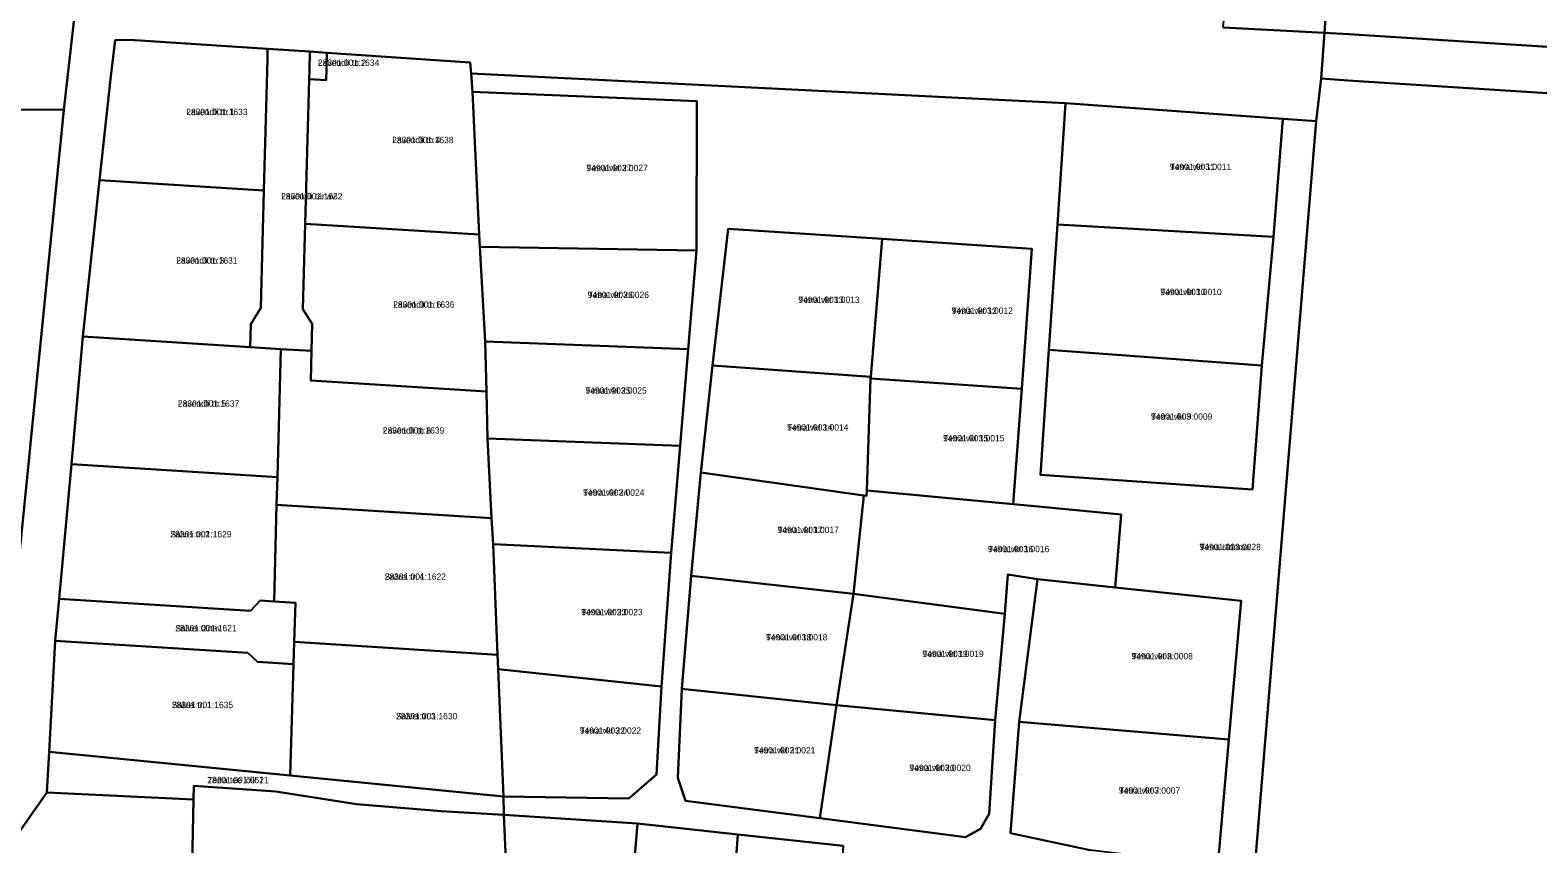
# Model space of a CAD drawing. Extents: x 647845 to 668483, y 6445298 to 6473683.
# Drawn here: x 653029 to 653385.7, y 6468442.7 to 6468635.3 of the extents above; entities that cross this region are included whole.
import ezdxf

# ---------------------------------------------------------------- set-up
doc = ezdxf.new("R2010")
doc.units = 0
for name, color, linetype in [('L_AADRESS', 7, 'Continuous'), ('PIIR', 7, 'Continuous'), ('TUNNUS', 7, 'Continuous')]:
    doc.layers.add(name, color=color, linetype=linetype)

msp = doc.modelspace()

# ---------------------------------------------------------------- linework, layer by layer
at = {"layer": 'PIIR'}
for points in [[(652338.93, 6468981.05), (652696.45, 6468730.7), (652794.83, 6468661.68), (653047.44, 6468736.3), (653049.27, 6468736.37), (653044.84, 6468694.9), (653040.96, 6468651.31), (653036.95, 6468616.44), (652921.22, 6468617.23), (652884.72, 6468617.47), (652848.22, 6468617.72), (652811.72, 6468617.97), (652775.22, 6468618.22), (652738.72, 6468618.47), (652702.23, 6468618.72), (652665.73, 6468618.96), (652629.23, 6468619.21), (652592.73, 6468619.46), (652556.23, 6468619.7), (652519.73, 6468619.96), (652483.23, 6468620.21), (652450.34, 6468620.43), (652403.65, 6468620.75), (652383.63, 6468708.25)], [(653025.07, 6468497.06), (653036.95, 6468616.44), (653040.96, 6468651.31)], [(653311.26, 6468635.95), (653335.23, 6468634.71), (653334.45, 6468623.86), (653333.23, 6468613.76), (653325.37, 6468614.34), (653273.95, 6468618.06), (653133.32, 6468625.06), (653133.14, 6468627.7), (653099.21, 6468629.97), (653095.18, 6468630.24), (653085.19, 6468630.9), (653052.6, 6468633.07), (653049.09, 6468632.99), (653048.14, 6468624.4), (653045.4, 6468599.8), (653041.46, 6468562.8), (653038.82, 6468532.6), (653035.87, 6468500.73), (653034.92, 6468490.77), (653033.49, 6468464.51), (653032.96, 6468454.83), (653015.66, 6468430.26)], [(653833.65, 6468592.05), (653340.7, 6468623.38), (653334.45, 6468623.86), (653335.23, 6468634.71), (653340.97, 6468634.35), (653661.32, 6468613.93)], [(653221.36, 6468442.23), (653196.46, 6468444.93), (653172.68, 6468447.5), (653141.05, 6468449.59), (653140.97, 6468453.86), (653170.63, 6468453.42), (653177.16, 6468459.07), (653178.36, 6468479.95), (653180.62, 6468511.57), (653182.76, 6468536.91), (653184.69, 6468559.77), (653186.67, 6468583.17), (653186.7, 6468618.5), (653133.63, 6468620.73), (653133.32, 6468625.06), (653273.95, 6468618.06), (653272.02, 6468589.3), (653270.03, 6468559.64), (653268.04, 6468530.08), (653318.16, 6468526.55), (653320.4, 6468555.9), (653323.12, 6468586.39), (653325.37, 6468614.34), (653333.23, 6468613.76), (653317.65, 6468423.77)], [(653710.59, 6468385.69), (653555.14, 6468400.78), (653531.19, 6468403.11), (653478.45, 6468408.19), (653472.23, 6468408.79), (653401.93, 6468415.57), (653339.11, 6468421.73), (653320.73, 6468423.39), (653317.65, 6468423.77), (653333.23, 6468613.76), (653334.45, 6468623.86), (653340.7, 6468623.38), (653833.65, 6468592.05)], [(653310.01, 6468437.56), (653312.6, 6468467.38), (653315.49, 6468500.22), (653285.66, 6468503.4), (653287.15, 6468520.69), (653267.46, 6468522.54), (653261.54, 6468523.1), (653263.61, 6468550.43), (653266.01, 6468583.55), (653230.6, 6468585.89), (653194.13, 6468588.29), (653190.47, 6468555.97), (653187.67, 6468530.64), (653185.36, 6468506.15), (653183.19, 6468479.41), (653182.21, 6468458.31), (653184.01, 6468452.89), (653215.79, 6468448.76), (653250.27, 6468444.31), (653253.8, 6468446.24), (653255.92, 6468449.81), (653257.34, 6468471.98), (653259.56, 6468497.15), (653260.27, 6468506.49), (653267.31, 6468505.34), (653262.98, 6468471.61), (653260.93, 6468445.19), (653279.74, 6468441.16)]]:
    msp.add_lwpolyline(points, dxfattribs=at)
for points in [[(653311.26, 6468635.95), (653312.47, 6468649.1), (653330.48, 6468649.07), (653333.16, 6468676.61), (653336.06, 6468705.49), (653338.28, 6468734.94), (653340.46, 6468764.79), (653342.62, 6468794.35), (653345.18, 6468824.85), (653347.75, 6468857.25), (653350.22, 6468888.19), (653352.64, 6468917.87), (653369.86, 6468979.89), (653374.26, 6468980.08), (653365.44, 6468948.31), (653356.91, 6468917.58), (653353.12, 6468866.71), (653346.11, 6468776.83), (653345.82, 6468772.19), (653342.65, 6468722.74), (653335.88, 6468644.68), (653335.23, 6468634.71)], [(653346.11, 6468776.83), (653515.43, 6468766.59), (653515.34, 6468764.64), (653676.65, 6468698.91), (653661.32, 6468613.93), (653340.97, 6468634.35), (653335.23, 6468634.71), (653335.88, 6468644.68), (653342.65, 6468722.74), (653345.82, 6468772.19)], [(653048.14, 6468624.4), (653049.09, 6468632.99), (653052.6, 6468633.07), (653085.19, 6468630.9), (653085.13, 6468628.35), (653084.3, 6468597.35), (653045.4, 6468599.8)], [(653085.13, 6468628.35), (653085.19, 6468630.9), (653095.18, 6468630.24), (653095.06, 6468625.69), (653095.01, 6468623.75), (653094.1, 6468589.49), (653093.56, 6468569.29), (653095.72, 6468565.76), (653095.55, 6468559.38), (653088.31, 6468559.84), (653081.07, 6468560.3), (653081.21, 6468565.7), (653083.56, 6468569.55), (653084.3, 6468597.35)], [(653099.1, 6468626.11), (653099.21, 6468629.97), (653133.14, 6468627.7), (653133.32, 6468625.06), (653133.63, 6468620.73), (653135.24, 6468586.92), (653094.1, 6468589.49), (653095.01, 6468623.75), (653099.03, 6468623.5)], [(653095.06, 6468625.69), (653095.18, 6468630.24), (653099.21, 6468629.97), (653099.1, 6468626.11), (653099.03, 6468623.5), (653095.01, 6468623.75)], [(653133.63, 6468620.73), (653186.7, 6468618.5), (653186.67, 6468583.17), (653135.39, 6468584.06), (653135.24, 6468586.92)], [(653036.95, 6468616.44), (653025.07, 6468497.06), (652877.52, 6468498.81), (652878.17, 6468554.05), (652895.58, 6468544.31), (652901.69, 6468544.29), (652901.61, 6468563.89), (652920.86, 6468563.77), (652921.22, 6468617.23)], [(653273.95, 6468618.06), (653325.37, 6468614.34), (653323.12, 6468586.39), (653272.02, 6468589.3)], [(653041.46, 6468562.8), (653045.4, 6468599.8), (653084.3, 6468597.35), (653083.56, 6468569.55), (653081.21, 6468565.7), (653081.07, 6468560.3)], [(653093.56, 6468569.29), (653094.1, 6468589.49), (653135.24, 6468586.92), (653135.39, 6468584.06), (653136.67, 6468561.62), (653136.94, 6468549.75), (653095.38, 6468552.37), (653095.55, 6468559.38), (653095.72, 6468565.76)], [(653194.13, 6468588.29), (653230.6, 6468585.89), (653227.86, 6468553.22), (653190.47, 6468555.97)], [(653272.02, 6468589.3), (653323.12, 6468586.39), (653320.4, 6468555.9), (653270.03, 6468559.64)], [(653135.39, 6468584.06), (653186.67, 6468583.17), (653184.69, 6468559.77), (653136.67, 6468561.62)], [(653266.01, 6468583.55), (653263.61, 6468550.43), (653227.85, 6468552.84), (653227.86, 6468553.22), (653230.6, 6468585.89)], [(653038.82, 6468532.6), (653041.46, 6468562.8), (653081.07, 6468560.3), (653088.31, 6468559.84), (653087.5, 6468529.53)], [(653136.94, 6468549.75), (653136.67, 6468561.62), (653184.69, 6468559.77), (653182.76, 6468536.91), (653137.18, 6468538.67)], [(653087.5, 6468529.53), (653088.31, 6468559.84), (653095.55, 6468559.38), (653095.38, 6468552.37), (653136.94, 6468549.75), (653137.18, 6468538.67), (653138.14, 6468519.78), (653087.31, 6468522.96)], [(653270.03, 6468559.64), (653320.4, 6468555.9), (653318.16, 6468526.55), (653268.04, 6468530.08)], [(653190.47, 6468555.97), (653227.86, 6468553.22), (653227.85, 6468552.84), (653226.91, 6468526.34), (653226.86, 6468525.09), (653226.25, 6468525.18), (653187.67, 6468530.64)], [(653227.85, 6468552.84), (653263.61, 6468550.43), (653261.54, 6468523.1), (653226.91, 6468526.34)], [(653138.14, 6468519.78), (653137.18, 6468538.67), (653182.76, 6468536.91), (653180.62, 6468511.57), (653138.57, 6468513.67)], [(653035.87, 6468500.73), (653038.82, 6468532.6), (653087.5, 6468529.53), (653087.31, 6468522.96), (653086.72, 6468500.06), (653083.45, 6468500.27), (653081.18, 6468497.88)], [(653187.67, 6468530.64), (653226.25, 6468525.18), (653223.82, 6468501.87), (653185.36, 6468506.15)], [(653259.56, 6468497.15), (653223.82, 6468501.87), (653226.25, 6468525.18), (653226.86, 6468525.09), (653226.91, 6468526.34), (653261.54, 6468523.1), (653267.46, 6468522.54), (653287.15, 6468520.69), (653285.66, 6468503.4), (653267.31, 6468505.34), (653260.27, 6468506.49)], [(653086.72, 6468500.06), (653087.31, 6468522.96), (653138.14, 6468519.78), (653138.57, 6468513.67), (653139.58, 6468487.44), (653091.49, 6468490.49), (653091.75, 6468499.74)], [(653139.73, 6468484.08), (653139.58, 6468487.44), (653138.57, 6468513.67), (653180.62, 6468511.57), (653178.36, 6468479.95)], [(653185.36, 6468506.15), (653223.82, 6468501.87), (653219.77, 6468475.55), (653183.19, 6468479.41)], [(653262.98, 6468471.61), (653267.31, 6468505.34), (653285.66, 6468503.4), (653315.49, 6468500.22), (653312.6, 6468467.38)], [(653034.92, 6468490.77), (653035.87, 6468500.73), (653081.18, 6468497.88), (653083.45, 6468500.27), (653086.72, 6468500.06), (653091.75, 6468499.74), (653091.49, 6468490.49), (653091.33, 6468485.24), (653082.77, 6468485.78), (653080.55, 6468487.9)], [(653223.82, 6468501.87), (653259.56, 6468497.15), (653257.34, 6468471.98), (653219.77, 6468475.55)], [(653033.49, 6468464.51), (653034.92, 6468490.77), (653080.55, 6468487.9), (653082.77, 6468485.78), (653091.33, 6468485.24), (653090.5, 6468458.86)], [(653091.33, 6468485.24), (653091.49, 6468490.49), (653139.58, 6468487.44), (653139.73, 6468484.08), (653140.97, 6468453.86), (653090.5, 6468458.86)], [(653170.63, 6468453.42), (653140.97, 6468453.86), (653139.73, 6468484.08), (653178.36, 6468479.95), (653177.16, 6468459.07)], [(653184.01, 6468452.89), (653182.21, 6468458.31), (653183.19, 6468479.41), (653219.77, 6468475.55), (653215.79, 6468448.76)], [(653257.34, 6468471.98), (653255.92, 6468449.81), (653253.8, 6468446.24), (653250.27, 6468444.31), (653215.79, 6468448.76), (653219.77, 6468475.55)], [(653279.74, 6468441.16), (653260.93, 6468445.19), (653262.98, 6468471.61), (653312.6, 6468467.38), (653310.01, 6468437.56)], [(653033.49, 6468464.51), (653090.5, 6468458.86), (653140.97, 6468453.86), (653141.05, 6468449.59), (653126.25, 6468450.45), (653106.19, 6468452.12), (653087.15, 6468455.12), (653067.74, 6468456.41), (653067.62, 6468453.16), (653032.96, 6468454.83)], [(653066.36, 6468392.28), (653048.9, 6468390.78), (653015.37, 6468392.4), (653015.66, 6468430.26), (653032.96, 6468454.83), (653067.62, 6468453.16)], [(653087.15, 6468455.12), (653106.19, 6468452.12), (653126.25, 6468450.45), (653141.05, 6468449.59), (653142.85, 6468409), (653140.61, 6468376.44), (653143.13, 6468374.95), (653143.07, 6468373.88), (653142.39, 6468357.49), (653141.94, 6468346.77), (653141.8, 6468343.37), (653141.18, 6468340.19), (653140.59, 6468337.22), (653138.12, 6468335.41), (653131.32, 6468332.4), (653088.65, 6468323.31), (653051.67, 6468315.43), (653041.08, 6468313.17), (653041.5, 6468317.18), (653045.72, 6468358.09), (653048.9, 6468390.78), (653066.36, 6468392.28), (653067.62, 6468453.16), (653067.74, 6468456.41)], [(653146.88, 6468372.74), (653140.61, 6468376.44), (653142.85, 6468409), (653141.05, 6468449.59), (653172.68, 6468447.5), (653166.64, 6468374.46)], [(653172.68, 6468447.5), (653196.46, 6468444.93), (653191.4, 6468376.17), (653166.64, 6468374.46)], [(653196.46, 6468444.93), (653221.36, 6468442.23), (653217.36, 6468377.95), (653194.36, 6468376.37), (653191.4, 6468376.17)]]:
    msp.add_lwpolyline(points, close=True, dxfattribs=at)

# ---------------------------------------------------------------- texts
at = {"layer": 'L_AADRESS'}
for s, p in [('Lavendli tn 2', (653097.11, 6468626.87)), ('Lavendli tn 1', (653065.95, 6468615.21)), ('Lavendli tn 4', (653114.67, 6468608.57)), ('Terra vkt 11', (653298.64, 6468602.23)), ('Terra vkt 27', (653160.61, 6468601.95)), ('Lavendli tänav', (653088.39, 6468595.26)), ('Lavendli tn 3', (653063.57, 6468580.05)), ('Terra vkt 26', (653160.9, 6468571.91)), ('Terra vkt 13', (653210.74, 6468570.75)), ('Terra vkt 10', (653296.39, 6468572.6)), ('Lavendli tn 6', (653114.89, 6468569.62)), ('Terra vkt 12', (653247, 6468568.16)), ('Terra vkt 25', (653160.38, 6468549.27)), ('Lavendli tn 5', (653063.98, 6468546.17)), ('Terra vkt 9', (653294.17, 6468543.1)), ('Lavendli tn 8', (653112.47, 6468539.81)), ('Terra vkt 14', (653208.09, 6468540.53)), ('Terra vkt 15', (653244.99, 6468537.97)), ('Terra vkt 24', (653159.82, 6468525.12)), ('Salvei tn 2', (653062.16, 6468515.24)), ('Terra vkt 17', (653205.82, 6468516.26)), ('Terra vkt 16', (653255.61, 6468511.74)), ('Terra üldmaa', (653305.66, 6468512.22)), ('Salvei tn 4', (653112.87, 6468505.2)), ('Terra vkt 23', (653159.39, 6468496.81)), ('Salvei tänav', (653063.35, 6468492.99)), ('Terra vkt 18', (653203.12, 6468490.85)), ('Terra vkt 19', (653240.09, 6468486.93)), ('Terra vkt 8', (653289.57, 6468486.36)), ('Salvei tn 1', (653062.53, 6468474.82)), ('Salvei tn 3', (653115.57, 6468472.17)), ('Terra vkt 22', (653159.04, 6468468.75)), ('Terra vkt 21', (653200.27, 6468464.09)), ('Terra vkt 20', (653237.01, 6468459.93)), ('Terra tee lõik 1', (653070.93, 6468457.05)), ('Terra vkt 7', (653286.57, 6468454.58))]:
    msp.add_text(s, height=1.5, dxfattribs=at).set_placement(p)
at = {"layer": 'TUNNUS'}
for s, p in [('28301:001:1634', (653097.11, 6468626.87)), ('28301:001:1633', (653065.95, 6468615.21)), ('28301:001:1638', (653114.67, 6468608.57)), ('94901:003:0027', (653160.61, 6468601.95)), ('94901:003:0011', (653298.64, 6468602.23)), ('28301:001:1632', (653088.39, 6468595.26)), ('28301:001:1631', (653063.57, 6468580.05)), ('94901:003:0026', (653160.9, 6468571.91)), ('94901:003:0013', (653210.74, 6468570.75)), ('94901:003:0010', (653296.39, 6468572.6)), ('28301:001:1636', (653114.89, 6468569.62)), ('94901:003:0012', (653247, 6468568.16)), ('94901:003:0025', (653160.38, 6468549.27)), ('28301:001:1637', (653063.98, 6468546.17)), ('94901:003:0009', (653294.17, 6468543.1)), ('28301:001:1639', (653112.47, 6468539.81)), ('94901:003:0014', (653208.09, 6468540.53)), ('94901:003:0015', (653244.99, 6468537.97)), ('94901:003:0024', (653159.82, 6468525.12)), ('28301:001:1629', (653062.16, 6468515.24)), ('94901:003:0017', (653205.82, 6468516.26)), ('94901:003:0016', (653255.61, 6468511.74)), ('94901:003:0028', (653305.66, 6468512.22)), ('28301:001:1622', (653112.87, 6468505.2)), ('94901:003:0023', (653159.39, 6468496.81)), ('28301:001:1621', (653063.35, 6468492.99)), ('94901:003:0018', (653203.12, 6468490.85)), ('94901:003:0019', (653240.09, 6468486.93)), ('94901:003:0008', (653289.57, 6468486.36)), ('28301:001:1635', (653062.53, 6468474.82)), ('28301:001:1630', (653115.57, 6468472.17)), ('94901:003:0022', (653159.04, 6468468.75)), ('94901:003:0021', (653200.27, 6468464.09)), ('94901:003:0020', (653237.01, 6468459.93)), ('28301:001:0521', (653070.93, 6468457.05)), ('94901:003:0007', (653286.57, 6468454.58))]:
    msp.add_text(s, height=1.5, dxfattribs=at).set_placement(p)

doc.saveas('drawing.dxf')
